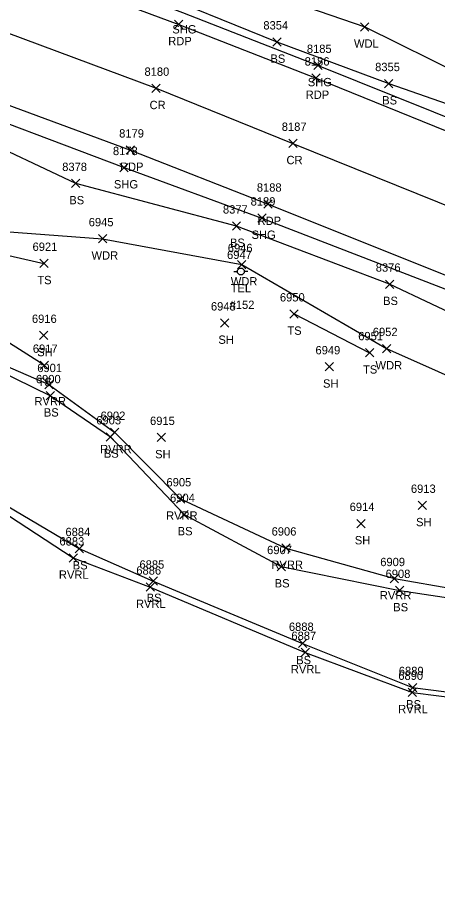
# Model space of a CAD drawing. Extents: x 1588028 to 1589597, y 137576 to 138176.
# Drawn here: x 1589205.2 to 1589306, y 137581.4 to 137792.6 of the extents above; entities that cross this region are included whole.
import ezdxf

# ---------------------------------------------------------------- set-up
doc = ezdxf.new("R2010")
doc.units = 0
for name, color, linetype in [('L_A', 7, 'Continuous'), ('L_I', 7, 'Continuous'), ('L_TIC', 7, 'Continuous'), ('LAWA', 7, 'Continuous'), ('LAWE', 7, 'Continuous'), ('LELB', 7, 'Continuous'), ('P_A', 7, 'Continuous'), ('P_I', 7, 'Continuous'), ('P_TIC', 7, 'Continuous'), ('PET', 7, 'Continuous'), ('PRC', 7, 'Continuous'), ('PSU', 7, 'Continuous'), ('U_A', 7, 'Continuous'), ('U_C', 7, 'Continuous'), ('U_I', 7, 'Continuous'), ('UP', 7, 'Continuous')]:
    doc.layers.add(name, color=color, linetype=linetype)

msp = doc.modelspace()

# ---------------------------------------------------------------- linework, layer by layer
at = {"layer": 'L_TIC'}
for points in [[(1589287.54, 137789.36), (1589289.54, 137791.36)], [(1589289.54, 137789.36), (1589287.54, 137791.36)], [(1589266.46, 137785.74), (1589268.46, 137787.74)], [(1589268.46, 137785.74), (1589266.46, 137787.74)], [(1589293.29, 137775.74), (1589295.29, 137777.74)], [(1589295.29, 137775.74), (1589293.29, 137777.74)], [(1589218.17, 137751.77), (1589220.17, 137753.77)], [(1589220.17, 137751.77), (1589218.17, 137753.77)], [(1589256.75, 137741.55), (1589258.75, 137743.55)], [(1589258.75, 137741.55), (1589256.75, 137743.55)], [(1589224.59, 137738.5), (1589226.59, 137740.5)], [(1589226.59, 137738.5), (1589224.59, 137740.5)], [(1589210.53, 137732.59), (1589212.53, 137734.59)], [(1589212.53, 137732.59), (1589210.53, 137734.59)], [(1589258.02, 137732.29), (1589260.02, 137734.29)], [(1589260.02, 137732.29), (1589258.02, 137734.29)], [(1589293.5, 137727.6), (1589295.5, 137729.6)], [(1589295.5, 137727.6), (1589293.5, 137729.6)], [(1589270.56, 137720.45), (1589272.56, 137722.45)], [(1589272.56, 137720.45), (1589270.56, 137722.45)], [(1589253.91, 137718.28), (1589255.91, 137720.28)], [(1589255.91, 137718.28), (1589253.91, 137720.28)], [(1589210.44, 137715.3), (1589212.44, 137717.3)], [(1589212.44, 137715.3), (1589210.44, 137717.3)], [(1589292.77, 137712.14), (1589294.77, 137714.14)], [(1589294.77, 137712.14), (1589292.77, 137714.14)], [(1589288.71, 137711.14), (1589290.71, 137713.14)], [(1589290.71, 137711.14), (1589288.71, 137713.14)], [(1589210.6, 137708.12), (1589212.6, 137710.12)], [(1589212.6, 137708.12), (1589210.6, 137710.12)], [(1589279.03, 137707.76), (1589281.03, 137709.76)], [(1589281.03, 137707.76), (1589279.03, 137709.76)], [(1589211.73, 137703.5), (1589213.73, 137705.5)], [(1589213.73, 137703.5), (1589211.73, 137705.5)], [(1589212.06, 137700.82), (1589214.06, 137702.82)], [(1589214.06, 137700.82), (1589212.06, 137702.82)], [(1589226.47, 137690.94), (1589228.47, 137692.94)], [(1589228.47, 137690.94), (1589226.47, 137692.94)], [(1589227.51, 137692.02), (1589229.51, 137694.02)], [(1589229.51, 137692.02), (1589227.51, 137694.02)], [(1589238.74, 137690.8), (1589240.74, 137692.8)], [(1589240.74, 137690.8), (1589238.74, 137692.8)], [(1589243.33, 137676.06), (1589245.33, 137678.06)], [(1589245.33, 137676.06), (1589243.33, 137678.06)], [(1589301.36, 137674.5), (1589303.36, 137676.5)], [(1589303.36, 137674.5), (1589301.36, 137676.5)], [(1589244.18, 137672.31), (1589246.18, 137674.31)], [(1589246.18, 137672.31), (1589244.18, 137674.31)], [(1589286.66, 137670.14), (1589288.66, 137672.14)], [(1589288.66, 137670.14), (1589286.66, 137672.14)], [(1589219, 137664.12), (1589221, 137666.12)], [(1589221, 137664.12), (1589219, 137666.12)], [(1589268.62, 137664.25), (1589270.62, 137666.25)], [(1589270.62, 137664.25), (1589268.62, 137666.25)], [(1589217.55, 137661.87), (1589219.55, 137663.87)], [(1589219.55, 137661.87), (1589217.55, 137663.87)], [(1589267.48, 137659.8), (1589269.48, 137661.8)], [(1589269.48, 137659.8), (1589267.48, 137661.8)], [(1589294.65, 137656.92), (1589296.65, 137658.92)], [(1589296.65, 137656.92), (1589294.65, 137658.92)], [(1589236.06, 137654.88), (1589238.06, 137656.88)], [(1589238.06, 137654.88), (1589236.06, 137656.88)], [(1589236.76, 137656.31), (1589238.76, 137658.31)], [(1589238.76, 137656.31), (1589236.76, 137658.31)], [(1589295.93, 137654.07), (1589297.93, 137656.07)], [(1589297.93, 137654.07), (1589295.93, 137656.07)], [(1589272.63, 137641.37), (1589274.63, 137643.37)], [(1589274.63, 137641.37), (1589272.63, 137643.37)], [(1589273.24, 137639.2), (1589275.24, 137641.2)], [(1589275.24, 137639.2), (1589273.24, 137641.2)], [(1589298.98, 137629.61), (1589300.98, 137631.61)], [(1589300.98, 137629.61), (1589298.98, 137631.61)], [(1589299.04, 137630.76), (1589301.04, 137632.76)], [(1589301.04, 137630.76), (1589299.04, 137632.76)]]:
    msp.add_lwpolyline(points, dxfattribs=at)
at = {"layer": 'LAWA'}
for points in [[(1589191.48, 137827.66), (1589208.47, 137821.19), (1589231.01, 137810.22), (1589260.79, 137799.99), (1589288.54, 137790.36), (1589312.49, 137778.55), (1589337.68, 137767.31), (1589356.85, 137760.89), (1589388.23, 137746.7), (1589420.91, 137733.88), (1589453.12, 137717.84), (1589474.94, 137709.38)], [(1589174.22, 137750.28), (1589194.61, 137741.77), (1589225.59, 137739.5), (1589259.02, 137733.29), (1589293.77, 137713.14), (1589318.53, 137702.11), (1589332.78, 137696.04)]]:
    msp.add_lwpolyline(points, dxfattribs=at)
at = {"layer": 'LAWE'}
for points in [[(1588998.37, 137781.01), (1589022.99, 137780.11), (1589053.11, 137769.29), (1589085.17, 137761.52), (1589118.32, 137748.59), (1589139.23, 137719.4), (1589162.49, 137704.02), (1589194.14, 137678.84), (1589218.55, 137662.87), (1589237.06, 137655.88), (1589274.24, 137640.2), (1589299.98, 137630.61), (1589325.3, 137627.35), (1589364.55, 137614.89), (1589400.15, 137603.63), (1589430.64, 137600.05), (1589464.28, 137596.09), (1589486.71, 137581.4)], [(1589165.8, 137734.64), (1589187.94, 137715.26), (1589212.73, 137704.5), (1589228.51, 137693.02), (1589244.33, 137677.06), (1589269.62, 137665.25), (1589295.65, 137657.92), (1589324.97, 137652.81), (1589365.32, 137641.86), (1589399.41, 137634.7), (1589423.88, 137632.18), (1589457.23, 137620.82), (1589479.74, 137612.88)]]:
    msp.add_lwpolyline(points, dxfattribs=at)
at = {"layer": 'LELB'}
for points in [[(1589158, 137835.46), (1589156.32, 137830.93), (1589175.62, 137825.43), (1589182.94, 137822.51), (1589209.46, 137809.41), (1589234.23, 137800.33), (1589267.46, 137786.74), (1589294.29, 137776.74), (1589322.35, 137767.05), (1589346.37, 137758.08), (1589352.86, 137754.06), (1589353.51, 137751.68), (1589354.61, 137751.57), (1589355.75, 137752.57)], [(1588992.37, 137810.47), (1589023.33, 137801.66), (1589065.26, 137783.21), (1589085.4, 137777.87), (1589097.27, 137780.08), (1589112.23, 137773.55), (1589130.4, 137758.11), (1589147.06, 137743.95), (1589161.02, 137733.26), (1589186.97, 137714.57), (1589213.06, 137701.82), (1589227.47, 137691.94), (1589245.18, 137673.31), (1589268.48, 137660.8), (1589296.93, 137655.07), (1589325.66, 137650.73)], [(1588992.54, 137792.39), (1589023.3, 137782.03), (1589052.1, 137771.44), (1589084.42, 137763.28), (1589121.54, 137752.14), (1589143.04, 137720.61), (1589163.05, 137704.95), (1589194.58, 137680.14), (1589220, 137665.12), (1589237.76, 137657.31), (1589273.63, 137642.37), (1589300.04, 137631.76), (1589324.52, 137628.67), (1589366.23, 137617.74), (1589400.05, 137606.05), (1589430.12, 137603.56), (1589464.26, 137598.64), (1589483.45, 137589.04)], [(1589346.98, 137708.09), (1589339.5, 137707.7), (1589337.39, 137703.26), (1589330.57, 137699.32), (1589318.71, 137707.48), (1589314.78, 137719.03), (1589294.5, 137728.6), (1589257.75, 137742.55), (1589219.17, 137752.77), (1589194.38, 137764.43), (1589173.98, 137767.54)], [(1589211.6, 137709.12), (1589193.1, 137720.87), (1589182.26, 137733.4), (1589195.69, 137737.14), (1589211.53, 137733.59)], [(1589271.56, 137721.45), (1589289.71, 137712.14)]]:
    msp.add_lwpolyline(points, dxfattribs=at)
at = {"layer": 'P_TIC'}
for points in [[(1589242.87, 137789.96), (1589244.87, 137791.96)], [(1589244.87, 137789.96), (1589242.87, 137791.96)], [(1589276.33, 137780.11), (1589278.33, 137782.11)], [(1589278.33, 137780.11), (1589276.33, 137782.11)], [(1589275.87, 137777.08), (1589277.87, 137779.08)], [(1589277.87, 137777.08), (1589275.87, 137779.08)], [(1589237.44, 137774.62), (1589239.44, 137776.62)], [(1589239.44, 137774.62), (1589237.44, 137776.62)], [(1589270.31, 137761.4), (1589272.31, 137763.4)], [(1589272.31, 137761.4), (1589270.31, 137763.4)], [(1589231.28, 137759.8), (1589233.28, 137761.8)], [(1589233.28, 137759.8), (1589231.28, 137761.8)], [(1589229.78, 137755.58), (1589231.78, 137757.58)], [(1589231.78, 137755.58), (1589229.78, 137757.58)], [(1589264.32, 137746.81), (1589266.32, 137748.81)], [(1589266.32, 137746.81), (1589264.32, 137748.81)], [(1589262.84, 137743.47), (1589264.84, 137745.47)], [(1589264.84, 137743.47), (1589262.84, 137745.47)]]:
    msp.add_lwpolyline(points, dxfattribs=at)
at = {"layer": 'PET'}
for points in [[(1588976.42, 137837.98), (1588964.71, 137855.4), (1588953.74, 137871.46), (1588980.82, 137866.91), (1589021.21, 137859.55), (1589054.58, 137852.92), (1589087.36, 137843.77), (1589127.64, 137831.45), (1589150.05, 137824.37), (1589196.14, 137808.72), (1589243.87, 137790.96), (1589276.87, 137778.08), (1589322.25, 137759.62), (1589367.82, 137740.82), (1589401.87, 137726.11), (1589432.81, 137712.85), (1589459.76, 137701.46)], [(1588976.42, 137837.98), (1589015.38, 137829.77), (1589047.77, 137821.87), (1589087.62, 137811.07), (1589117.34, 137801.67), (1589165.82, 137785.25), (1589185.23, 137778.17), (1589232.28, 137760.8), (1589265.32, 137747.81), (1589310.31, 137729.83), (1589359.63, 137709.23), (1589389.55, 137696.8), (1589422.31, 137682.69), (1589446.91, 137672.54)]]:
    msp.add_lwpolyline(points, dxfattribs=at)
at = {"layer": 'PRC'}
msp.add_lwpolyline([(1588964.71, 137855.4), (1588980.14, 137852.51), (1589018.19, 137844.35), (1589051.57, 137836.27), (1589092.27, 137825.07), (1589122.68, 137816.23), (1589170.7, 137800.29), (1589190.72, 137793.38), (1589238.44, 137775.62), (1589271.31, 137762.4), (1589315.94, 137744.35), (1589366.22, 137723.58), (1589395.71, 137710.87), (1589428.18, 137697.42), (1589453.33, 137686.42)], dxfattribs=at)
at = {"layer": 'PSU'}
for points in [[(1589152.74, 137827.96), (1589197.07, 137811.88), (1589244.81, 137793.79), (1589277.33, 137781.11), (1589323.36, 137762.65), (1589353.23, 137749.52), (1589368.68, 137743.62), (1589402.84, 137728.77), (1589433.2, 137714.7), (1589460.72, 137703.44)], [(1589136.35, 137790.83), (1589164.04, 137781.22), (1589184.55, 137774.07), (1589230.78, 137756.58), (1589263.84, 137744.47), (1589309.17, 137726.92), (1589358.43, 137707.04), (1589387.87, 137693.92), (1589420.52, 137679.79), (1589445.83, 137669.38)]]:
    msp.add_lwpolyline(points, dxfattribs=at)
at = {"layer": 'UP'}
for p, q in [((1589257.13, 137731.65), (1589257.96, 137731.65)), ((1589258.79, 137731.65), (1589258.79, 137731.65)), ((1589260.46, 137731.65), (1589259.62, 137731.65)), ((1589259.62, 137731.65), (1589259.62, 137731.65)), ((1589260.46, 137731.65), (1589260.46, 137731.65))]:
    msp.add_line(p, q, dxfattribs=at)
msp.add_circle((1589258.79, 137731.65), 0.833, dxfattribs=at)

# ---------------------------------------------------------------- texts
at = {"layer": 'L_A'}
for s, p in [('WDL', (1589285.95, 137785.36)), ('BS', (1589265.9, 137781.74)), ('BS', (1589292.73, 137771.74)), ('BS', (1589217.61, 137747.77)), ('BS', (1589256.19, 137737.55)), ('WDR', (1589222.95, 137734.5)), ('TS', (1589209.94, 137728.59)), ('WDR', (1589256.38, 137728.29)), ('BS', (1589292.94, 137723.6)), ('TS', (1589269.97, 137716.45)), ('SH', (1589253.4, 137714.28)), ('SH', (1589209.92, 137711.3)), ('WDR', (1589291.13, 137708.14)), ('TS', (1589288.12, 137707.14)), ('TS', (1589210.01, 137704.12)), ('SH', (1589278.51, 137703.76)), ('RVRR', (1589209.25, 137699.5)), ('BS', (1589211.5, 137696.82)), ('RVRR', (1589225.02, 137688.02)), ('BS', (1589225.91, 137686.94)), ('SH', (1589238.22, 137686.8)), ('RVRR', (1589240.84, 137672.06)), ('SH', (1589300.85, 137670.5)), ('BS', (1589243.63, 137668.31)), ('SH', (1589286.15, 137666.14)), ('BS', (1589218.44, 137660.12)), ('RVRR', (1589266.14, 137660.25)), ('RVRL', (1589215.12, 137657.87)), ('BS', (1589266.92, 137655.8)), ('RVRR', (1589292.16, 137652.92)), ('RVRL', (1589233.63, 137650.88)), ('BS', (1589236.2, 137652.31)), ('BS', (1589295.37, 137650.07)), ('BS', (1589272.08, 137637.37)), ('RVRL', (1589270.8, 137635.2)), ('RVRL', (1589296.55, 137625.61)), ('BS', (1589298.48, 137626.76))]:
    msp.add_text(s, height=2, dxfattribs=at).set_placement(p)
at = {"layer": 'L_I'}
for s, p in [('8354', (1589264.2, 137789.74)), ('8355', (1589291.03, 137779.74)), ('8378', (1589215.91, 137755.77)), ('8377', (1589254.49, 137745.55)), ('6945', (1589222.28, 137742.5)), ('6921', (1589208.79, 137736.59)), ('6946', (1589255.66, 137736.29)), ('8376', (1589291.18, 137731.6)), ('6950', (1589268.17, 137724.45)), ('6948', (1589251.61, 137722.28)), ('6916', (1589208.64, 137719.3)), ('6952', (1589290.47, 137716.14)), ('6951', (1589286.97, 137715.14)), ('6917', (1589208.86, 137712.12)), ('6949', (1589276.71, 137711.76)), ('6901', (1589209.92, 137707.5)), ('6900', (1589209.59, 137704.82)), ('6903', (1589224.09, 137694.94)), ('6902', (1589225.12, 137696.02)), ('6915', (1589236.99, 137694.8)), ('6905', (1589240.94, 137680.06)), ('6913', (1589299.62, 137678.5)), ('6904', (1589241.8, 137676.31)), ('6914', (1589284.92, 137674.14)), ('6884', (1589216.69, 137668.12)), ('6906', (1589266.18, 137668.25)), ('6883', (1589215.25, 137665.87)), ('6907', (1589265.1, 137663.8)), ('6909', (1589292.26, 137660.92)), ('6886', (1589233.7, 137658.88)), ('6885', (1589234.46, 137660.31)), ('6908', (1589293.54, 137658.07)), ('6888', (1589270.33, 137645.37)), ('6887', (1589270.93, 137643.2)), ('6890', (1589296.59, 137633.61)), ('6889', (1589296.72, 137634.76))]:
    msp.add_text(s, height=2, dxfattribs=at).set_placement(p)
at = {"layer": 'P_A'}
for s, p in [('SHG', (1589242.34, 137788.79)), ('RDP', (1589241.36, 137785.96)), ('SHG', (1589274.87, 137776.11)), ('RDP', (1589274.36, 137773.08)), ('CR', (1589236.88, 137770.62)), ('CR', (1589269.75, 137757.4)), ('RDP', (1589229.77, 137755.8)), ('SHG', (1589228.32, 137751.58)), ('RDP', (1589262.81, 137742.81)), ('SHG', (1589261.37, 137739.47))]:
    msp.add_text(s, height=2, dxfattribs=at).set_placement(p)
at = {"layer": 'P_I'}
for s, p in [('8185', (1589274.64, 137784.11)), ('8186', (1589274.12, 137781.08)), ('8180', (1589235.66, 137778.62)), ('8187', (1589268.62, 137765.4)), ('8179', (1589229.58, 137763.8)), ('8178', (1589228.09, 137759.58)), ('8188', (1589262.63, 137750.81)), ('8189', (1589261.14, 137747.47))]:
    msp.add_text(s, height=2, dxfattribs=at).set_placement(p)
at = {"layer": 'U_A'}
msp.add_text('TEL', height=2, dxfattribs=at).set_placement((1589256.35, 137726.65))
at = {"layer": 'U_C'}
msp.add_text('#152', height=2, dxfattribs=at).set_placement((1589256.1, 137722.65))
at = {"layer": 'U_I'}
msp.add_text('6947', height=2, dxfattribs=at).set_placement((1589255.48, 137734.65))

doc.saveas('drawing.dxf')
